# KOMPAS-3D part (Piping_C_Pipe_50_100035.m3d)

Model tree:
1. Plane XY
2. Plane ZX
3. Plane ZY
4. X Axis
5. Y Axis
6. Z Axis
7. Origin
8. Path  (labels: Труба Dy 50; Отвод 90 Dy 50)
9. Plane of section
10. Section of pipe
11. Pipe
     Толщина стенки 1 = 1

Referenced files in C:\Program Files\ASCON\KOMPAS-3D V10\Libs\Piping\Models\Tanks\: Tanks.a3d
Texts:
  Pipe Dn 50
  Steel ASTM A295
  Three Point Plane
  Plane at Angle
  Line and Point Plane
  Axis through Two Vertices
  Axis of Feature
  Axis of Conical Surface
  Axis through Edge
  Приклеить элемент выдавливания
  Приклеить элемент вращения
  Приклеить кинематический элемент
  Приклеить элемент по сечениям
  Trim by Surface
  Trim by Sketch
  Feature with No History
  Intersection Axis of Two Planes
  Two Line Plane
  Line and Face Plane
  Bend by line
  Hole in sheet body
  Cut in sheet body
  Point in CM
  Linear Dimension from Line to Point
  Surface Finish Symbol
  Geometric Tolerance Symbol
  Текст на чертеже
  Линия-выноска #1
  Линия-выноска #2
  Линия-выноска #3
  Отклонения формы и база
  Марка координационной оси
  Марка/позиционное обозначение с линией-выноской
  Марка/позиционное обозначение на линии
  Марка/позиционное обозначение без линии-выноски
  Труба Dy 50
  Отвод 90 Dy 50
